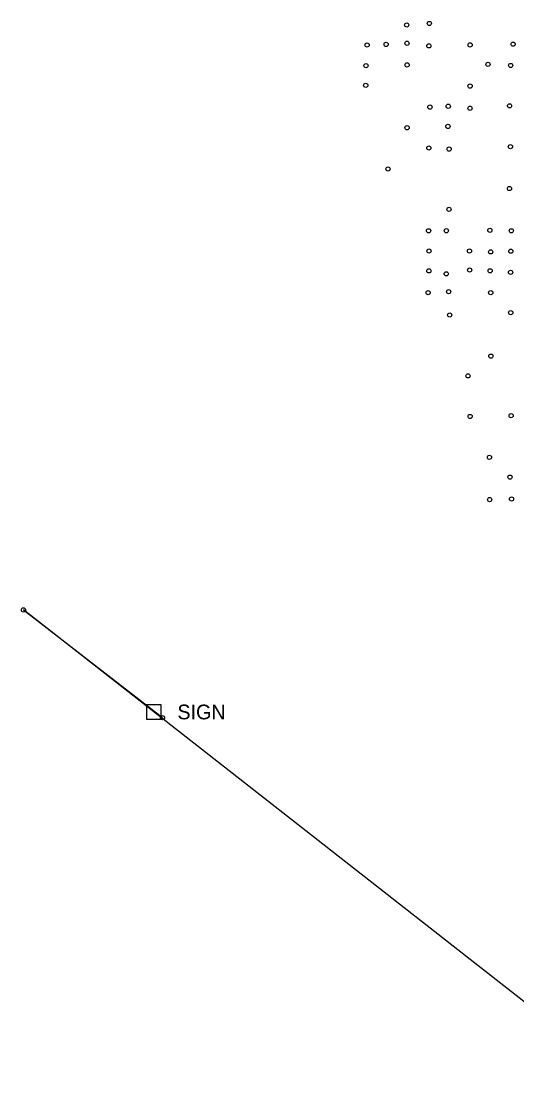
# Model space of a CAD drawing. Extents: x 20503438 to 20508873, y 7964251 to 7984667.
# Drawn here: x 20505323 to 20505559, y 7976408 to 7976916 of the extents above; entities that cross this region are included whole.
import ezdxf

# ---------------------------------------------------------------- set-up
doc = ezdxf.new("R2010")
doc.units = 0
for name, color, linetype in [('SurFenceWire', 7, 'Continuous'), ('SurPointsNonDTM', 7, 'Continuous'), ('SurRoadPoints', 7, 'Continuous'), ('SurSurveyPoints', 7, 'Continuous')]:
    doc.layers.add(name, color=color, linetype=linetype)

msp = doc.modelspace()

# ---------------------------------------------------------------- linework, layer by layer
at = {"layer": 'SurFenceWire'}
msp.add_lwpolyline([(20505734.71, 7976316.24), (20505684.99, 7976354.55), (20505628.9, 7976398.01), (20505569.42, 7976444.2), (20505324.2, 7976636.22), (20505390.28, 7976584.99)], dxfattribs=at)
at = {"layer": 'SurPointsNonDTM'}
for centre in [(20505324.2, 7976636.22), (20505390.28, 7976584.99)]:
    msp.add_circle(centre, 1, dxfattribs=at)
at = {"layer": 'SurRoadPoints'}
msp.add_lwpolyline([(20505386.18, 7976584.24), (20505386.18, 7976584.24), (20505389.61, 7976584.24), (20505389.61, 7976591.1), (20505382.75, 7976591.1), (20505382.75, 7976584.24), (20505386.18, 7976584.24)], dxfattribs=at)
at = {"layer": 'SurSurveyPoints'}
for centre in [(20505506.38, 7976914.5), (20505517.13, 7976915.21), (20505496.6, 7976905.25), (20505506.53, 7976905.79), (20505556.95, 7976905.36), (20505487.55, 7976904.98), (20505516.92, 7976904.54), (20505536.53, 7976905), (20505487.01, 7976895.11), (20505506.58, 7976895.5), (20505545.02, 7976895.77), (20505555.82, 7976895.23), (20505486.91, 7976885.75), (20505536.51, 7976885.43), (20505517.4, 7976875.43), (20505526.12, 7976875.83), (20505536.48, 7976874.87), (20505555.27, 7976876.03), (20505506.56, 7976865.61), (20505525.96, 7976866.24), (20505516.89, 7976855.97), (20505526.55, 7976855.45), (20505555.68, 7976856.6), (20505497.47, 7976845.99), (20505555.22, 7976836.67), (20505526.5, 7976826.76), (20505516.77, 7976816.58), (20505525.23, 7976816.6), (20505545.9, 7976816.79), (20505556.09, 7976816.58), (20505516.95, 7976806.96), (20505536.2, 7976806.99), (20505546.27, 7976806.56), (20505555.88, 7976806.86), (20505516.92, 7976797.52), (20505525.17, 7976796.11), (20505536.28, 7976797.91), (20505546.02, 7976797.55), (20505555.76, 7976796.8), (20505516.57, 7976787.14), (20505526.32, 7976787.63), (20505546.33, 7976787.17), (20505526.8, 7976776.51), (20505555.84, 7976777.65), (20505546.38, 7976756.96), (20505535.54, 7976747.55), (20505536.53, 7976728.25), (20505556.02, 7976728.64), (20505545.72, 7976708.81), (20505555.5, 7976699.4), (20505545.81, 7976688.71), (20505556.21, 7976688.96)]:
    msp.add_circle(centre, 1, dxfattribs=at)

# ---------------------------------------------------------------- texts
at = {"layer": 'SurRoadPoints'}
msp.add_text('SIGN', height=6.995, rotation=360, dxfattribs=at).set_placement((20505397.39, 7976584.17))

doc.saveas('drawing.dxf')
